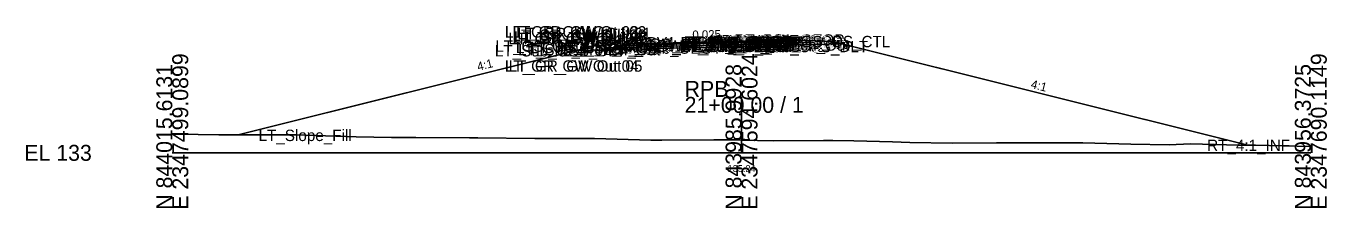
# Model space of a CAD drawing. Extents: x -76 to 2347760, y -10 to 844216.
# Drawn here: x -25.7 to 202.8, y 5990.3 to 6022.3 of the extents above; entities that cross this region are included whole.
import ezdxf

# ---------------------------------------------------------------- set-up
doc = ezdxf.new("R2010")
doc.units = 0
for name, color, linetype in [('Default', 7, 'Continuous'), ('Exist Cross Section Cell', 7, 'Continuous'), ('Exist XS Center Line Elevation Label', 7, 'Continuous'), ('Exist XS Ground Line', 7, 'Continuous'), ('Prop CMT Pvmt Course 1', 7, 'Continuous'), ('Prop CMT Pvmt Course 2', 7, 'Continuous'), ('Prop CMT Pvmt Course 3', 7, 'Continuous'), ('Prop CMT Pvmt Surface', 7, 'Continuous'), ('Prop CMT Pvmt Surface Shoulder', 7, 'Continuous'), ('Prop CMT Shld Paved Course 1', 7, 'Continuous'), ('Prop CMT Shld Paved Course 2', 7, 'Continuous'), ('Prop CMT Shld Paved Course 3', 7, 'Continuous'), ('Prop CMT Slope Grass', 7, 'Continuous'), ('Prop CMT Subgrade Earthwork', 7, 'Continuous'), ('Prop XS Earthwork Shape', 7, 'Continuous'), ('Prop XS SE Text', 7, 'Continuous'), ('Prop XS Side Slope Text', 7, 'Continuous'), ('Scratch_Level_0', 7, 'Continuous')]:
    doc.layers.add(name, color=color, linetype=linetype)

msp = doc.modelspace()

# ---------------------------------------------------------------- linework, layer by layer
at = {"layer": 'Exist Cross Section Cell'}
for p, q in [((100, 6000), (100, 6009.83)), ((0, 6000), (100, 6000)), ((100, 6000), (200, 6000))]:
    msp.add_line(p, q, dxfattribs=at)
at = {"layer": 'Exist XS Ground Line'}
msp.add_lwpolyline([(0, 6003.27), (0.89, 6003.28), (8.17, 6003.15), (11.36, 6003.15), (18.46, 6003.15), (21.83, 6003.14), (23.35, 6003.11), (32.3, 6002.82), (38.52, 6002.71), (42.77, 6002.68), (52.22, 6002.65), (53.24, 6002.66), (53.7, 6002.64), (63.71, 6002.52), (68.88, 6002.53), (74.18, 6002.51), (84.05, 6002.25), (84.65, 6002.23), (85.99, 6002.24), (95.12, 6002.27), (99.23, 6002.26), (100, 6002.24), (105.59, 6002.12), (114.41, 6002.17), (116.06, 6002.18), (119.75, 6002.09), (126.53, 6001.91), (129.58, 6001.81), (137, 6001.7), (144.76, 6001.77), (147.47, 6001.74), (153.51, 6001.76), (157.94, 6001.75), (159.94, 6001.73), (168.41, 6001.52), (175.11, 6001.42), (178.88, 6001.57), (187.27, 6001.34), (189.35, 6001.32), (190.29, 6001.34), (200, 6001.14)], dxfattribs=at)
at = {"layer": 'Prop CMT Pvmt Course 1'}
for p, q in [((100, 6019.63), (88, 6019.33)), ((100, 6019.63), (104, 6019.73)), ((100, 6019.38), (100, 6019.63)), ((100, 6019.38), (100, 6019.63)), ((104, 6019.73), (104, 6019.48)), ((88, 6019.08), (100, 6019.38)), ((88, 6019.33), (88, 6019.08)), ((100, 6019.38), (100, 6019.5)), ((100, 6019.5), (100, 6019.5)), ((100, 6019.5), (100, 6019.38)), ((100, 6019.38), (100, 6019.5)), ((100, 6019.5), (100, 6019.5)), ((100, 6019.5), (100, 6019.38)), ((104, 6019.48), (100, 6019.38)), ((100, 6019.38), (100, 6019.38)), ((100, 6019.38), (100, 6019.38))]:
    msp.add_line(p, q, dxfattribs=at)
at = {"layer": 'Prop CMT Pvmt Course 2'}
for p, q in [((100, 6019.38), (88, 6019.08)), ((88, 6019.08), (88, 6018.74)), ((88, 6018.74), (100, 6019.04)), ((100, 6019.38), (104, 6019.48)), ((100, 6019.04), (100, 6019.38)), ((100, 6019.04), (100, 6019.38)), ((104, 6019.14), (100, 6019.04)), ((104, 6019.48), (104, 6019.14))]:
    msp.add_line(p, q, dxfattribs=at)
at = {"layer": 'Prop CMT Pvmt Course 3'}
for p, q in [((100, 6019.04), (88, 6018.74)), ((88, 6018.74), (88, 6018.41)), ((88, 6018.41), (100, 6018.71)), ((100, 6019.04), (104, 6019.14)), ((100, 6018.71), (100, 6019.04)), ((100, 6018.71), (100, 6019.04)), ((104, 6018.81), (100, 6018.71)), ((104, 6019.14), (104, 6018.81))]:
    msp.add_line(p, q, dxfattribs=at)
at = {"layer": 'Prop CMT Pvmt Surface'}
for q in [(88, 6019.33), (104, 6019.73)]:
    msp.add_line((100, 6019.63), q, dxfattribs=at)
at = {"layer": 'Prop CMT Pvmt Surface Shoulder'}
for p, q in [((104, 6019.73), (108, 6019.83)), ((88, 6019.33), (78, 6019.08))]:
    msp.add_line(p, q, dxfattribs=at)
at = {"layer": 'Prop CMT Shld Paved Course 1'}
for p, q in [((104, 6019.73), (108, 6019.83)), ((104, 6019.48), (104, 6019.73)), ((108.24, 6019.58), (104, 6019.48)), ((108, 6019.83), (108.24, 6019.58)), ((78, 6019.08), (77.74, 6018.82)), ((77.74, 6018.82), (88, 6019.08)), ((88, 6019.33), (78, 6019.08)), ((88, 6019.08), (88, 6019.33))]:
    msp.add_line(p, q, dxfattribs=at)
at = {"layer": 'Prop CMT Shld Paved Course 2'}
for p, q in [((104, 6019.48), (108.24, 6019.58)), ((108.24, 6019.58), (108.57, 6019.26)), ((77.74, 6018.82), (77.4, 6018.48)), ((77.4, 6018.48), (88, 6018.74)), ((88, 6019.08), (77.74, 6018.82)), ((88, 6018.74), (88, 6019.08)), ((104, 6019.14), (104, 6019.48)), ((108.57, 6019.26), (104, 6019.14))]:
    msp.add_line(p, q, dxfattribs=at)
at = {"layer": 'Prop CMT Shld Paved Course 3'}
for p, q in [((76.9, 6018.47), (76.56, 6018.12)), ((76.56, 6018.12), (88, 6018.41)), ((77.4, 6018.48), (76.9, 6018.47)), ((88, 6018.74), (77.4, 6018.48)), ((88, 6018.41), (88, 6018.74)), ((104, 6019.14), (108.57, 6019.26)), ((104, 6018.81), (104, 6019.14)), ((109.39, 6018.95), (104, 6018.81)), ((108.57, 6019.26), (109.07, 6019.27)), ((109.07, 6019.27), (109.39, 6018.95))]:
    msp.add_line(p, q, dxfattribs=at)
at = {"layer": 'Prop CMT Slope Grass'}
for p, q in [((108, 6019.83), (116, 6019.55)), ((74, 6018.76), (11.57, 6003.15)), ((78, 6019.08), (74, 6018.76)), ((116, 6019.55), (188.91, 6001.32))]:
    msp.add_line(p, q, dxfattribs=at)
at = {"layer": 'Prop CMT Subgrade Earthwork'}
for p, q in [((76.56, 6018.12), (70.9, 6017.98)), ((88, 6018.41), (76.56, 6018.12)), ((100, 6018.71), (88, 6018.41)), ((100, 6018.71), (104, 6018.81)), ((104, 6018.81), (117.59, 6019.15))]:
    msp.add_line(p, q, dxfattribs=at)
at = {"layer": 'Prop XS Earthwork Shape'}
msp.add_lwpolyline([(100, 6018.71), (104, 6018.81), (117.59, 6019.15), (188.91, 6001.32), (187.27, 6001.34), (178.88, 6001.57), (175.11, 6001.42), (168.41, 6001.52), (159.94, 6001.73), (157.94, 6001.75), (153.51, 6001.76), (147.47, 6001.74), (144.76, 6001.77), (137, 6001.7), (129.58, 6001.81), (126.53, 6001.91), (119.75, 6002.09), (116.06, 6002.18), (114.41, 6002.17), (105.59, 6002.12), (100, 6002.24), (99.23, 6002.26), (95.12, 6002.27), (85.99, 6002.24), (84.65, 6002.23), (84.05, 6002.25), (74.18, 6002.51), (68.88, 6002.53), (63.71, 6002.52), (53.7, 6002.64), (53.24, 6002.66), (52.22, 6002.65), (42.77, 6002.68), (38.52, 6002.71), (32.3, 6002.82), (23.35, 6003.11), (21.83, 6003.14), (18.46, 6003.15), (11.57, 6003.15), (70.9, 6017.98), (76.56, 6018.12), (88, 6018.41)], close=True, dxfattribs=at)

# ---------------------------------------------------------------- texts
at = {"layer": 'Default'}
msp.add_text('-', height=0.0001, dxfattribs=at).set_placement((0, 6000))
at = {"layer": 'Exist Cross Section Cell'}
for s, p in [('E 2347499.0899', (2.8, 5990)), ('E 2347594.6024', (102.8, 5990)), ('E 2347690.1149', (202.8, 5990)), ('N 844015.6131', (0, 5990)), ('N 843985.9928', (100, 5990)), ('N 843956.3725', (200, 5990))]:
    msp.add_text(s, height=2.8, rotation=90, dxfattribs=at).set_placement(p)
for s, p in [('RPB', (90, 6009.83)), ('21+00.00 / 1', (90, 6007.03)), ('EL 133', (-26, 5998.6))]:
    msp.add_text(s, height=2.8, dxfattribs=at).set_placement(p)
at = {"layer": 'Exist XS Center Line Elevation Label'}
msp.add_text('135.24', height=1.2, dxfattribs=at).set_placement((97.55, 5996.64))
at = {"layer": 'Prop XS SE Text'}
msp.add_text('0.025', height=1.5, rotation=1.4321, dxfattribs=at).set_placement((91.38, 6019.98))
at = {"layer": 'Prop XS Side Slope Text'}
for rotation, p in [(14.0362, (53.75, 6014.4)), (345.9638, (150.72, 6011.41))]:
    msp.add_text('4:1', height=1.5, rotation=rotation, dxfattribs=at).set_placement(p)
at = {"layer": 'Scratch_Level_0'}
for s, p in [('LT_GR_GW Out 03', (58.43, 6020.26)), ('LT_GR_GW Out 02', (59.77, 6020.26)), ('LT_GR_GW Out 01', (60.6, 6019.97)), ('LT_GS_OS_GR_Face_GW', (56.75, 6017.76)), ('LT_GR_GW Out 06', (59.05, 6019.09)), ('LT_GR_GW Out 09', (59.77, 6019.67)), ('LT_GR_GW Out 07', (59.77, 6019.09)), ('LT_GR_GW Out 08', (60.04, 6019.38)), ('LT_PS3_Shelf_Out', (62.89, 6017.47)), ('LT_PS2_OEOP', (67.98, 6017.82)), ('LT_PS1_OEOP', (68.8, 6018.08)), ('LT_PV2_OEOT', (78.17, 6018.08)), ('LT_PV3_OEOT', (78.17, 6017.74)), ('LT_PV1_OEOT', (78.74, 6018.33)), ('RT_Sub_OEEOP', (89.17, 6017.71)), ('LT_Sub_OEEOP', (89.21, 6017.71)), ('RT_PV2_OEEOP', (89.26, 6018.38)), ('RT_PV3_OEEOP', (89.26, 6018.04)), ('LT_PV2_OEEOP', (89.31, 6018.38)), ('LT_PV3_OEEOP', (89.31, 6018.04)), ('RT_PV1_OEEOP', (89.83, 6018.5)), ('LT_PV1_OEEOP', (89.87, 6018.5)), ('RT_PV2_IEEOP', (89.91, 6018.38)), ('LT_PV2_IEEOP', (89.95, 6018.38)), ('RT_PV1_IEEOP', (90.47, 6018.5)), ('LT_PV1_IEEOP', (90.52, 6018.5)), ('RT_Sub_Trench_Out', (93.55, 6017.95)), ('PV2_PGL', (93.91, 6018.38)), ('RT_Sub_OEOT', (94.03, 6017.81)), ('RT_PV2_OEOT', (94.13, 6018.48)), ('RT_PV3_OEOT', (94.13, 6018.14)), ('PV1_PGL', (94.47, 6018.63)), ('RT_PV1_OEOT', (94.69, 6018.73)), ('RT_PS3_Shelf_Out', (95.01, 6018.27)), ('RT_PS2_OEOP', (98.43, 6018.58)), ('RT_Sub_OSS_DLT', (98.75, 6017.68)), ('RT_PS1_OEOP', (98.76, 6018.83)), ('RT_PS3_OEOP', (98.76, 6018.26)), ('RT_GS_OS_CTL', (105.32, 6018.55)), ('LT_Sub_OSS_DLT', (56.67, 6016.94)), ('LT_GS_OS_CTL', (60.36, 6017.52)), ('LT_Sub_Trench_Out', (60.76, 6017.12)), ('LT_PS3_OEOP', (67.64, 6017.48)), ('LT_Sub_OEOT', (78.08, 6017.41)), ('LT_GR_GW Out 04', (58.43, 6014.26)), ('LT_GR_GW Out 05', (59.1, 6014.26)), ('LT_Slope_Fill', (15.16, 6002.07)), ('RT_4:1_INF', (181.79, 6000.32))]:
    msp.add_text(s, height=2, dxfattribs=at).set_placement(p)

doc.saveas('drawing.dxf')
